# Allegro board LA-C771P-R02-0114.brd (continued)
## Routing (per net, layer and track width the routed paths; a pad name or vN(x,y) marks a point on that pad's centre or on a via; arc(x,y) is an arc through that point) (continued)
DDR_A_D25: length 48
  IN1 w0.127: v3(86.27,43.82) 86.27,42.6 85.79,42.13 85.79,39.88 85.58,39.67 85.11,39.67 84.91,39.87 84.91,42.49 84.43,42.98 84.43,44.87 83.93,45.36 83.93,52.24 85.1,53.41 85.1,55.96 90.15,61.02 90.15,64.42 91.04,65.31 v3(91.04,66.18)
  BOTTOM w0.102: v3(91.04,66.18) 91.72,66.86 92.06,66.86 93.44,68.24 94.73,68.24 96.98,70.49 97.52,70.49 97.66,70.35 97.98,70.35 98.14,70.51 98.45,70.51 UC4.C41 ; JDIMM1.59 84.53,45.64 86.27,43.91 v3(86.27,43.82)
DDR_A_D26: length 47.1
  IN1 w0.127: v3(93.73,65.38) 93.73,64.91 94.87,63.77 94.87,62.18 88.45,55.75 88.45,55.57 88.68,55.34 88.86,55.34 90.36,56.83 90.54,56.83 90.77,56.6 90.77,56.42 88.64,54.29 88.64,51.47 88.51,51.34 88.18,51.34 88.06,51.47 88.06,54.79 87.93,54.92 87.62,54.92 87.47,54.77 87.47,47.05 88.72,45.8 88.72,44.88 v3(88.22,44.38)
  BOTTOM w0.102: v3(88.22,44.38) 87.76,44.38 87.38,44.76 87.38,44.78 87.26,44.91 87.26,45.42 86.93,45.74 JDIMM1.67 ; v3(93.73,65.38) 93.73,65.7 95.95,67.92 95.95,68.1 96.78,68.93 97.34,68.93 97.57,68.7 UC4.A45
DDR_A_D27: length 47.1
  IN1 w0.127: v3(88.6,43.11) 89.3,43.81 89.3,46.27 88.06,47.52 88.06,50.62 88.19,50.75 88.96,50.75 89.22,51.02 89.22,53.98 95.09,59.85 95.09,60.03 94.84,60.28 94.66,60.28 91.64,57.26 91.46,57.26 91.21,57.51 91.21,57.69 95.46,61.93 95.46,64.02 94.34,65.14 v3(94.34,65.38)
  BOTTOM w0.102: UC4.B46 98.24,68.38 97.61,68.38 97.29,68.7 96.87,68.7 96.42,68.25 96.42,68 94.34,65.92 v3(94.34,65.38) ; JDIMM1.69 87.53,45.93 87.81,45.65 87.81,45.14 88.02,44.94 88.45,44.94 88.78,44.61 88.78,43.29 v3(88.6,43.11)
DDR_A_D28: length 48.4
  IN1 w0.127: v3(88.98,64.72) 88.98,61.5 83.93,56.45 83.93,53.89 82.76,52.73 82.76,49.28 81.72,48.24 81.72,45.35 82.11,44.96 82.11,42.74 82.86,41.99 82.86,39.41 83.05,39.21 83.33,39.21 83.52,39.41 83.52,40.97 83.76,41.2 v3(84.18,41.2)
  BOTTOM w0.102: v3(88.98,64.72) 88.98,65.49 89.34,65.84 89.34,66.46 90.86,67.98 92.47,67.98 93.22,68.74 94.54,68.74 96.78,70.98 97.96,70.98 98.15,70.79 98.31,70.79 98.65,71.13 UC4.C40 ; v3(84.18,41.2) 83.63,40.65 JDIMM1.56
DDR_A_D29: length 48.1
  IN1 w0.127: v3(88.4,65.92) 88.4,61.74 84.43,57.78 83.68,57.78 83.34,57.45 83.34,54.14 82.18,52.97 82.18,49.52 81.13,48.48 81.13,45.1 81.53,44.71 81.53,42.5 81.78,42.24 81.78,38.81 82.04,38.55 83.75,38.55 84.23,39.03 v3(84.23,39.91)
  BOTTOM w0.102: v3(88.4,65.92) 88.4,66.31 90.69,68.6 92.78,68.6 93.15,68.97 94.44,68.97 96.67,71.19 98.16,71.19 UC4.B40 ; JDIMM1.58 v3(84.23,39.91)
DDR_A_D30: length 46.5
  IN1 w0.127: v3(87.59,40.03) 87,39.44 87,39.1 87.21,38.88 87.55,38.88 88.34,39.67 88.34,40.54 89.83,42.03 90.01,42.03 90.25,41.79 90.25,41.61 89.53,40.89 89.53,40.71 89.76,40.48 89.94,40.48 90.86,41.4 90.86,45.82 89.81,46.87 89.81,47.83 89.68,47.95 89.09,47.95 88.96,48.08 88.96,48.41 89.09,48.54 89.68,48.54 89.81,48.67 89.81,49.13 89.68,49.26 88.79,49.26 88.64,49.41 88.64,49.68 88.8,49.84 89.68,49.84 89.81,49.97 89.81,53.72 96.04,59.95 96.04,64.92 v3(95.53,65.44)
  BOTTOM w0.102: JDIMM1.68 87.23,39.68 v3(87.59,40.03) ; v3(95.53,65.44) 95.53,66.44 96.58,67.49 98.05,67.49 98.43,67.11 UC4.B48
DDR_A_D31: length 47.1
  IN1 w0.102: 96.04,65.84 96.63,65.26 96.63,64.45
  IN1 w0.127: v3(89.03,40.29) 89.77,39.55 89.77,38.43 89.9,38.3 90.23,38.3 90.36,38.43 90.36,39.41 90.48,39.54 90.81,39.54 90.94,39.41 90.94,38.43 91.07,38.3 91.4,38.3 91.53,38.43 91.53,39.41 92,39.89 92,41.99 91.44,42.55 91.44,46.25 90.39,47.3 90.39,53.17 96.63,59.4 96.63,64.45 ; 96.04,65.84 95.79,66.1 95.18,66.1 94.93,65.84 v3(94.93,65.38)
  BOTTOM w0.102: v3(89.03,40.29) 88.83,40.29 88.17,39.63 87.83,39.29 JDIMM1.70 ; v3(94.93,65.38) 94.99,65.45 94.99,66.19 96.73,67.93 96.73,68.15 96.91,68.33 97.34,68.33 97.5,68.18 97.96,68.18 98.19,67.95 98.19,67.83 UC4.B47
DDR_A_D32: length 47.6
  IN1 w0.102: v3(102.34,62.57) 100.8,62.57 100.35,62.11
  IN1 w0.127: 100.35,62.11 100.08,61.84 99.3,61.84 98.84,61.37 98.84,58.8 92.14,52.1 92.14,50.04 93.08,49.1 93.08,47.36 94.63,45.82 97.82,45.82 98.5,45.14 98.5,43.25 99.07,42.68 101.28,42.68 101.67,42.28 106.58,42.28 107.24,41.63 107.58,41.63 107.86,41.91 107.86,42.54 107.55,42.85 v3(107.55,43.65)
  BOTTOM w0.102: v3(102.34,62.57) 102.57,62.79 102.57,64.11 102.36,64.32 102.36,65.02 UC4.K52 ; JDIMM1.129 107.93,46.01 107.17,45.24 107.17,44.73 107.25,44.66 107.25,44 107.55,43.69 v3(107.55,43.65)
DDR_A_D33: length 48.4
  IN1 w0.127: v3(107.78,44.91) 107.22,44.35 107.22,44.19 106.84,43.81 106.84,43 106.71,42.87 106.38,42.87 105.93,43.33 105.93,44.38 105.7,44.61 105.35,44.61 105.05,44.32 105.05,43.33 104.72,42.99 101.79,42.99 101.52,43.26 100.76,43.26 100.42,43.61 100.42,44.56 98.58,46.4 94.87,46.4 93.95,47.32 93.95,49.83 93.82,49.96 93.06,49.96 92.93,50.08 92.93,50.41 93.06,50.54 93.82,50.54 93.95,50.67 93.95,51 93.82,51.12 93.18,51.12 93.06,51.25 93.06,51.84 93.19,51.98 93.6,51.98 93.73,52.1 93.73,52.86 99.42,58.55 99.42,60.18 101.29,62.04 v3(101.99,62.04)
  BOTTOM w0.102: v3(101.99,62.04) 102.38,62.04 102.77,62.44 102.77,64.23 102.56,64.44 102.56,64.79 102.7,64.93 102.7,65.11 102.48,65.32 102.48,65.6 UC4.K51 ; JDIMM1.131 108.53,45.77 107.78,45.01 v3(107.78,44.91)
DDR_A_D34: length 48.5
  IN1 w0.127: v3(112,45.22) 112,46.8 109.21,49.59 107.65,49.59 107.52,49.46 107.52,49.26 107.4,49.14 107.07,49.14 106.94,49.26 106.94,49.46 106.81,49.59 106.36,49.59 104.54,51.4 104.01,51.4 103.84,51.57 103.84,52.03 104.87,53.06 104.87,53.24 104.64,53.47 104.46,53.47 102.57,51.58 102.39,51.58 102.18,51.79 102.18,52.02 104.05,53.89 104.05,54.15 103.86,54.33 103.67,54.33 100.23,50.9 100.05,50.9 99.82,51.12 99.82,51.32 102.5,54 102.5,54.18 102.27,54.41 102.09,54.41 101.56,53.88 101.38,53.88 101.15,54.11 101.15,54.29 102.06,55.21 103.33,55.21 103.67,55.56 103.67,56.6 v3(103.25,57.02)
  BOTTOM w0.102: v3(112,45.22) 111.92,45.22 111.53,45.6 JDIMM1.141 ; v3(103.25,57.02) 103.25,57.02 103.36,57.12 103.36,58.34 105.38,60.36 105.38,63.44 105.27,63.55 105.27,65.02 UC4.T52
DDR_A_D35: length 49.4
  IN1 w0.127: v3(103.09,56.29) 102.58,56.29 102.14,55.84 101.72,55.84 97.49,51.61 97.49,51.43 97.72,51.2 97.99,51.2 100.41,53.62 100.59,53.62 100.85,53.35 100.85,53.17 98.33,50.65 98.33,50.47 98.81,50 99.14,50 99.45,50.31 101.1,50.31 101.6,50.82 104.3,50.82 106.57,48.54 107.83,48.54 108.29,49 108.97,49 111.41,46.56 111.41,44.43 v3(111.94,43.9)
  BOTTOM w0.102: v3(111.94,43.9) 112.48,44.43 112.48,44.93 112.58,45.04 112.58,45.5 112.13,45.94 JDIMM1.143 ; UC4.T51 105.28,65.44 105.59,65.13 105.59,64.93 105.48,64.81 105.48,64.2 105.94,63.74 105.94,60.13 104.04,58.24 104.04,56.78 103.55,56.29 v3(103.09,56.29)
DDR_A_D36: length 48.5
  IN1 w0.127: v3(108.77,41.56) 108.77,41.09 108.38,40.7 107.34,40.7 106.34,41.7 101.43,41.7 101.04,42.09 98.82,42.09 97.88,43.04 95.3,43.04 93.44,44.9 93.44,46.09 92.5,47.04 92.5,48.86 91.56,49.8 91.56,52.43 v3(98.2,59.07)
  BOTTOM w0.102: v3(108.77,41.56) 108.23,41.02 JDIMM1.130 ; UC4.L51 103.03,65.2 103.03,64.91 103.31,64.63 103.31,62 102.51,61.19 101.12,61.19 101.12,61.19 100.18,60.25 99.51,60.25 98.34,59.07 v3(98.2,59.07)
DDR_A_D37: length 47.5
  IN1 w0.127: v3(108.83,39.91) 108.41,39.49 100.6,39.49 97.64,42.46 94.95,42.46 92.86,44.55 92.86,45.65 91.92,46.59 91.92,48.61 90.98,49.55 90.98,52.93 97.4,59.35 97.4,59.75 97.89,60.24 v3(98.26,60.24)
  BOTTOM w0.102: UC4.L53 103.04,64.45 103.04,62.11 102.34,61.42 100.56,61.42 99.95,60.81 98.83,60.81 v3(98.26,60.24) ; JDIMM1.132 v3(108.83,39.91)
DDR_A_D38: length 48.9
  IN1 w0.127: v3(101.41,57.59) 101,57.59 95.74,52.33 95.74,50.47 98.02,48.19 99.81,48.19 100.17,48.56 101.03,48.56 101.4,48.19 102.6,48.19 104,46.79 108.7,46.79 109.66,45.83 109.66,43.7 109.99,43.37 109.99,42.69 109.42,42.12 109.42,38.12 109.74,37.79 110.91,37.79 111.23,38.11 v3(111.23,39.91)
  BOTTOM w0.102: v3(111.23,39.91) JDIMM1.140 ; v3(101.41,57.59) 101.82,57.59 105.07,60.84 105.07,64.8 105.04,64.83 104.91,64.96 104.87,65 104.87,65.3 UC4.R51
DDR_A_D39: length 48.6
  IN1 w0.127: v3(101.43,58.32) 101.5,58.32 102.1,57.73 102.1,57.46 101.65,57.01 101.24,57.01 96.32,52.09 96.32,50.72 98.26,48.77 99.56,48.77 99.93,49.14 101.28,49.14 101.64,48.77 102.84,48.77 104.24,47.38 108.94,47.38 110.24,46.08 110.24,43.95 110.57,43.62 110.57,42.45 110,41.88 110,38.93 110.13,38.8 110.52,38.8 110.65,38.93 110.65,41.07 110.77,41.2 v3(111.22,41.2)
  BOTTOM w0.102: v3(101.43,58.32) 101.76,58.32 104.8,61.36 104.8,64.32 UC4.R53 ; v3(111.22,41.2) 111.23,41.2 111.83,40.6 JDIMM1.142
DDR_A_D40: length 48.3
  IN1 w0.102: v3(104.8,67.14) 104.16,66.5 104.16,65.65 103.77,65.26 103.77,65.06
  IN1 w0.127: 103.77,65.06 103.77,64.95 103.65,64.83 102.32,64.83 102.17,64.68 102.17,64.19 102.37,63.99 102.87,63.99 103.12,64.24 103.71,64.24 103.84,64.11 103.84,61.48 103.68,61.32 103.05,61.32 102.93,61.19 102.93,60.86 103.05,60.73 103.67,60.73 103.8,60.6 103.8,60.28 103.67,60.15 103.08,60.15 102.95,60.02 102.95,59.69 103.08,59.57 103.59,59.57 103.85,59.3 103.85,58.2 105.42,56.63 105.42,56.45 105.26,56.28 105.26,56.1 105.49,55.87 105.67,55.87 105.84,56.04 106.02,56.04 106.25,55.8 106.25,55.62 105.64,55.01 105.64,54.83 105.87,54.6 106.05,54.6 106.66,55.21 106.84,55.21 107.08,54.98 107.08,54.8 106.49,54.21 106.49,54.03 106.73,53.8 106.91,53.8 107.49,54.38 107.67,54.38 107.9,54.15 107.9,53.97 107.1,53.16 107.1,52.99 107.3,52.79 107.55,52.79 108.32,53.56 108.5,53.56 108.67,53.39 108.67,53.08 108.12,52.53 108.12,52.29 108.31,52.1 108.51,52.1 108.83,52.42 109.01,52.42 109.22,52.21 109.22,51.98 108.43,51.19 108.43,50.96 108.64,50.75 108.82,50.75 109.68,51.61 109.86,51.61 110.09,51.38 110.09,51.2 109.77,50.88 109.77,50.7 110.01,50.47 110.19,50.47 110.43,50.71 110.61,50.71 110.85,50.48 110.85,50.3 110.6,50.05 110.6,49.87 113.52,46.95 113.52,46.44 113.33,46.25 113.33,45.89 113.52,45.7 113.52,45.17 113.33,44.99 v3(113.33,44.57)
  BOTTOM w0.102: JDIMM1.147 v3(113.33,44.57) ; UC4.T47 v3(104.8,67.14)
DDR_A_D41: length 47.3
  IN1 w0.127: v3(113.34,43.29) 112.75,43.88 112.75,46.88 109.45,50.17 106.89,50.17 106.71,50.35 106.71,50.76 107.68,51.73 107.68,51.91 107.45,52.14 107.27,52.14 106.07,50.95 105.82,50.95 105.62,51.15 105.62,51.33 106.68,52.38 106.68,52.56 106.45,52.8 106.27,52.8 105.26,51.79 105.06,51.79 104.84,52.01 104.84,52.19 105.62,52.98 105.62,54.01 104.45,55.18 104.45,56.78 103.27,57.96 103.27,58.21 102.27,59.21 102.27,61.4 103.05,62.18 103.05,63.02 102.77,63.3 100.82,63.3 100.67,63.45 100.67,64.14 102.14,65.61 103.06,65.61 103.28,65.83 103.28,66.8 103.88,67.41 104.31,67.41 v3(104.81,67.91)
  BOTTOM w0.102: JDIMM1.149 113.93,43.88 v3(113.34,43.29) ; UC4.T45 v3(104.81,67.91)
DDR_A_D42: length 47
  IN1 w0.102: 107.17,67.48 107.17,69.37 107.31,69.51 107.31,70.82 v3(106.72,71.41)
  IN1 w0.127: v3(117.25,43.79) 118.02,43.79 118.29,44.07 118.29,45.44 118.86,46.01 119.81,46.01 120.69,46.89 120.69,50.86 120.11,51.44 120.11,51.8 119.71,52.21 119.53,52.21 119.24,51.92 119.06,51.92 118.83,52.15 118.83,52.33 119.06,52.57 119.06,52.86 117.4,54.52 113.45,54.52 107.98,59.98 107.98,63.67 108.14,63.82 108.49,63.82 108.64,63.97 108.64,64.72 108.34,65.01 108.34,66.24 108.21,66.37 107.89,66.37 107.75,66.23 107.75,65.12 107.58,64.95 107.31,64.95 107.17,65.09 107.17,67.48
  BOTTOM w0.102: v3(117.25,43.79) 116.33,44.72 JDIMM1.157 ; UC4.Y40 v3(106.72,71.41)
DDR_A_D43: length 48.1
  IN1 w0.102: v3(106.74,70.78) 106.8,70.78 107.1,70.48 107.1,69.71 106.81,69.42 106.51,69.42 106.2,69.12 106.2,65.87 106.44,65.63 106.44,65.19
  IN1 w0.127: 106.44,65.19 106.44,65.02 106.81,64.65 106.81,64.43 106.44,64.06 106.44,63.84 106.72,63.56 107.18,63.56 107.4,63.34 107.4,59.67 113.13,53.93 116.22,53.93 116.57,53.59 116.75,53.59 117.03,53.88 117.21,53.88 117.45,53.65 117.45,53.47 117.16,53.18 117.16,53 117.39,52.76 117.57,52.76 117.86,53.05 118.04,53.05 118.24,52.85 118.24,51.91 118.94,51.22 118.94,47.41 119.09,47.26 119.4,47.26 119.52,47.39 119.52,50.6 119.65,50.72 119.98,50.72 120.11,50.6 120.11,47.14 119.57,46.59 118.62,46.59 117.71,45.68 117.71,45.18 117.54,45 117.24,45 v3(117.08,45.17)
  BOTTOM w0.102: JDIMM1.159 116.93,45.36 117.08,45.22 v3(117.08,45.17) ; UC4.V41 v3(106.74,70.78)
DDR_A_D44: length 48.3
  IN1 w0.102: v3(104.78,66.51) 104.43,66.16 104.43,62.11 104.44,62.11
  IN1 w0.127: 104.44,62.11 104.44,58.44 111.44,51.44 111.44,49.86 114.1,47.2 114.1,43.12 113.68,42.7 112.12,42.7 111.84,42.42 111.84,37.02 111.72,36.89 109.95,36.89 109.82,36.76 109.82,36.43 109.95,36.3 112.32,36.3 112.71,36.69 112.71,40.65 v3(112.58,40.77)
  BOTTOM w0.102: UC4.T48 v3(104.78,66.51) ; JDIMM1.146 113.03,40.32 v3(112.58,40.77)
DDR_A_D45: length 48.3
  IN1 w0.102: v3(104.82,65.9) 104.82,64.63 105.02,64.42 105.02,62.11
  IN1 w0.127: v3(114,41.28) 114,39.34 114.13,39.21 115.42,39.21 115.56,39.07 115.56,38.75 115.43,38.63 114.13,38.63 114,38.5 114,38.17 114.13,38.04 115.35,38.04 115.48,37.91 115.48,37.58 115.35,37.46 113.6,37.46 113.42,37.64 113.42,41.15 113.11,41.46 112.58,41.46 112.43,41.61 112.43,41.99 112.55,42.12 113.93,42.12 114.69,42.88 114.69,47.44 112.02,50.1 112.02,51.68 105.02,58.68 105.02,62.11
  BOTTOM w0.102: JDIMM1.148 113.63,40.25 113.8,40.42 113.8,40.9 114,41.1 v3(114,41.28) ; UC4.T50 v3(104.82,65.9)
DDR_A_D46: length 48.3
  IN1 w0.102: 109.24,67.48 109.24,68.32 109.03,68.53 108.43,68.53 107.71,69.24 v3(107.71,69.5)
  IN1 w0.127: v3(117.23,41.48) 117.69,41.48 118.16,41.95 118.16,42.21 117.69,42.68 117.69,42.86 117.93,43.09 118.11,43.09 118.58,42.62 118.83,42.62 119.55,43.33 119.55,44.92 121.28,46.65 121.28,51.47 117.64,55.1 113.69,55.1 108.6,60.19 108.6,63.01 109.24,63.64 109.24,65.11 109.36,65.23 110.46,65.23 110.59,65.36 110.59,65.73 110.43,65.89 109.36,65.89 109.24,66.01 109.24,66.34 109.36,66.47 110.14,66.47 110.27,66.6 110.27,66.93 110.14,67.05 109.36,67.05 109.24,67.18 109.24,67.48
  BOTTOM w0.102: UC4.Y42 v3(107.71,69.5) ; v3(117.23,41.48) 116.63,40.88 JDIMM1.158
DDR_A_D47: length 48.1
  IN1 w0.102: 109.62,68.48 109.26,68.84 108.68,68.84 108.17,69.35 108.17,70.45 107.73,70.88 v3(107.73,70.89)
  IN1 w0.127: v3(117.25,39.96) 117.25,38.82 117.38,38.7 117.94,38.7 118.07,38.82 118.07,41.03 120.13,43.09 120.13,44.53 121.86,46.26 121.86,51.71 117.88,55.69 113.93,55.69 109.19,60.43 109.19,62.77 111.47,65.05 111.47,66.63 109.62,68.48
  BOTTOM w0.102: v3(117.25,39.96) 117.25,39.93 117.23,39.91 JDIMM1.160 ; UC4.AB40 v3(107.73,70.89)
DDR_A_D48: length 46.8
  IN2 w0.102: 110.6,63.3 110.25,63.65 109.49,63.65 107.5,65.63 107.5,66.29 107.5,66.35 107.25,66.6 107.25,67.72 v3(106.73,68.25)
  IN2 w0.127: v3(118.78,43.74) 119.12,43.74 119.32,43.94 119.32,45.81 120.96,47.46 120.96,50.47 120.83,50.59 120.5,50.59 120.38,50.47 120.38,47.7 120.24,47.57 119.92,47.57 119.79,47.69 119.79,54.28 117.38,56.69 117.13,56.69 116.97,56.53 116.97,56.28 117.64,55.6 117.64,55.39 117.5,55.24 117.18,55.24 115.73,56.69 114.24,56.69 111.44,59.5 111.44,60.79 110.93,61.29 110.93,62.97 110.6,63.3
  BOTTOM w0.102: JDIMM1.163 118.13,44.39 v3(118.78,43.74) ; UC4.V45 v3(106.73,68.25)
DDR_A_D49: length 48.8
  IN2 w0.102: v3(106.73,67.49) 107.05,67.17 107.05,66.48 107.3,66.23 107.3,65.5 109.48,63.32 109.9,63.32 110.19,63.02
  IN2 w0.127: 110.19,63.02 110.45,62.77 110.45,61.94 110.34,61.84 110.34,61.05 110.85,60.55 110.85,59.26 114.11,56 115.59,56 118.04,53.55 118.04,46.92 118.21,46.75 118.45,46.75 118.62,46.92 118.62,53.8 117.97,54.45 117.97,54.63 118.2,54.87 118.38,54.87 119.21,54.04 119.21,46.53 118.7,46.02 118.29,46.02 118.14,45.87 118.14,45.49 118.36,45.27 v3(118.71,45.27)
  BOTTOM w0.102: v3(118.71,45.27) 118.73,45.29 JDIMM1.165 ; UC4.V47 v3(106.73,67.49)
DDR_A_D50: length 48.8
  IN2 w0.102: 110.71,66.31 110.33,66.31 109.21,67.42 v3(108.75,67.42)
  IN2 w0.127: 110.71,66.31 112.59,66.31 126.56,52.33 126.56,47.38 126.43,47.26 125.3,47.26 125.15,47.11 125.15,46.8 125.28,46.67 126.55,46.67 126.68,46.55 126.68,46.22 126.55,46.09 125.38,46.09 125.2,45.9 125.2,44.14 124.99,43.93 124.75,43.93 124.57,44.11 124.57,45.62 124.42,45.76 124.18,45.76 123.19,44.77 123.19,44.31 123.46,44.04 123.46,43.29 122.73,42.56 122.53,42.56 122.25,42.83 122.25,43.23 v3(122.74,43.72)
  BOTTOM w0.102: UC4.AD48 v3(108.75,67.42) ; JDIMM1.175 121.73,45.14 121.98,44.89 121.98,44.25 122.51,43.72 v3(122.74,43.72)
DDR_A_D51: length 48.4
  IN2 w0.102: v3(108.74,66.69) 109.23,66.2 109.85,66.2 110.4,65.65 111.11,65.65
  IN2 w0.127: 111.11,65.65 112.42,65.65 115.22,62.85 115.22,62.67 114.58,62.03 114.58,61.82 114.78,61.62 115,61.62 115.63,62.25 115.81,62.25 116.05,62.02 116.05,61.84 115.8,61.59 115.8,61.41 116,61.22 116.25,61.22 116.46,61.43 116.64,61.43 116.87,61.19 116.87,61.01 116.68,60.82 116.68,60.62 116.87,60.43 117.12,60.43 117.29,60.6 117.46,60.6 124.62,53.44 124.62,53.25 124.5,53.12 123.72,53.12 123.6,52.99 123.6,52.68 123.74,52.54 124.5,52.54 124.62,52.41 124.62,52.16 124.75,52.03 125.71,52.03 125.84,51.9 125.84,51.57 125.71,51.44 124.75,51.44 124.62,51.32 124.62,50.99 124.75,50.86 125.78,50.86 125.91,50.73 125.91,50.41 125.77,50.28 124.75,50.28 124.62,50.15 124.62,49.82 124.75,49.69 125.77,49.69 125.9,49.56 125.9,49.24 125.77,49.11 124.75,49.11 124.62,48.98 124.62,48.65 124.75,48.52 125.77,48.52 125.9,48.4 125.9,48.07 125.77,47.94 124.71,47.94 124.58,47.81 124.58,47.23 124.45,47.1 124.14,47.1 123.84,47.41 123.65,47.41 123.42,47.18 123.42,47 123.84,46.58 123.84,46.26 123.47,45.88 123.1,45.88 v3(122.43,45.22)
  BOTTOM w0.102: v3(122.43,45.22) 122.43,45.6 122.33,45.7 JDIMM1.177 ; UC4.AD50 v3(108.74,66.69)
DDR_A_D52: length 46.8
  IN2 w0.102: 109.42,62.51 109.42,63.02 107.1,65.34 107.1,66.14 106.67,66.57 v3(106.67,66.67)
  IN2 w0.127: 109.42,62.51 109.42,59.87 113.86,55.42 115.35,55.42 117.46,53.31 117.46,45.35 117.87,44.93 117.87,43.82 117.17,43.12 117.17,42.22 117.85,41.54 117.85,39.15 117.66,38.95 115.5,38.95 115.37,38.83 115.37,38.52 115.52,38.37 118.18,38.37 118.55,38.74 118.55,41.2 118.81,41.46 v3(119.14,41.46)
  BOTTOM w0.102: v3(119.14,41.46) 118.43,40.75 JDIMM1.164 ; UC4.V48 v3(106.67,66.67)
DDR_A_D53: length 48.4
  IN2 w0.102: 108.65,63.42 106.71,65.36 v3(106.71,65.97)
  IN2 w0.127: v3(119.14,39.93) 119.14,38.29 118.64,37.79 118.34,37.79 118.21,37.66 118.21,37.03 118.08,36.91 117.75,36.91 117.63,37.03 117.63,37.66 117.5,37.79 117.17,37.79 117.04,37.66 117.04,37.03 116.91,36.91 116.58,36.91 116.46,37.03 116.46,37.66 116.33,37.79 116,37.79 115.87,37.66 115.87,37.03 115.75,36.91 115.42,36.91 115.29,37.03 115.29,37.66 114.78,38.16 114.78,39.16 115.16,39.54 116.36,39.54 116.62,39.8 116.62,40.82 115.12,42.33 115.12,44.76 116.87,46.51 116.87,53.07 115.1,54.84 113.62,54.84 108.83,59.63 108.83,63.24 108.65,63.42
  BOTTOM w0.102: JDIMM1.166 119.03,39.83 v3(119.14,39.93) ; UC4.V50 v3(106.71,65.97)
DDR_A_D54: length 48.5
  IN2 w0.102: 111.33,66.91 110.47,66.91 108.67,68.71 v3(107.69,68.71)
  IN2 w0.127: v3(121.58,39.93) 121.58,38.15 121.72,38.01 122.08,38.01 122.21,38.14 122.21,41.22 123.61,42.61 124.5,42.61 125.49,43.61 126.1,43.61 126.78,44.29 126.78,45.24 127.54,45.99 127.54,52.18 112.81,66.91 111.33,66.91
  BOTTOM w0.102: v3(121.58,39.93) 121.43,39.79 JDIMM1.174 ; UC4.AB44 v3(107.69,68.71)
DDR_A_D55: length 48.7
  IN2 w0.102: v3(106.75,68.91) 107.32,68.91 107.5,69.09 107.86,69.09 108,68.95 108.93,68.95 110.25,67.63 111.29,67.63
  IN2 w0.127: 111.29,67.63 112.92,67.63 128.3,52.24 128.3,44.77 126.55,43.02 125.74,43.02 125.36,42.65 125.36,41.1 125.23,40.97 124.85,40.97 124.73,41.1 124.73,41.8 124.5,42.03 123.91,42.03 v3(122.8,40.92)
  BOTTOM w0.102: JDIMM1.176 122.03,39.6 122.18,39.75 122.18,40.3 v3(122.8,40.92) ; UC4.Y45 v3(106.75,68.91)
DDR_A_D56: length 49.1
  IN1 w0.127: v3(124.11,43.57) 122.7,42.15 122.28,42.15 121.99,42.45 121.99,45.57 122.45,46.02 122.45,50.55 122.57,50.68 122.88,50.68 123.03,50.53 123.03,46.34 123.16,46.22 123.49,46.22 123.61,46.34 123.61,50.79 118.12,56.28 114.25,56.28 v3(110.34,60.18)
  BOTTOM w0.102: UC4.V52 106.17,64.94 106.17,63.26 109.38,60.05 110.22,60.05 v3(110.34,60.18) ; JDIMM1.181 123.53,44.15 v3(124.11,43.57)
DDR_A_D57: length 48.6
  IN1 w0.127: v3(124.13,44.98) 123.35,44.2 123.06,44.2 122.92,44.34 122.92,45.39 123.17,45.63 123.73,45.63 124.2,46.1 124.2,52.68 120.19,56.68 120.01,56.68 119.8,56.47 119.8,56.25 123.6,52.45 123.6,52.27 123.37,52.04 123.18,52.04 118.26,56.96 114.44,56.96 110.61,60.79 110.12,60.79 v3(109.89,60.56)
  BOTTOM w0.102: v3(109.89,60.56) 109.78,60.56 108.83,61.51 108.45,61.51 106.45,63.51 106.45,64.8 106.58,64.92 106.58,65.22 UC4.W51 ; JDIMM1.183 v3(124.13,44.98)
DDR_A_D58: length 49.8
  IN1 w0.102: v3(113.54,62.73) 114.06,62.73 115.18,61.62 115.18,61.31 115.38,61.1
  IN1 w0.127: v3(128.12,42.63) 128.12,42.86 127.67,43.32 127.67,43.44 128.12,43.9 128.12,55.42 127.44,56.1 127.44,56.35 127.62,56.53 128.58,56.53 128.7,56.4 128.7,54.71 128.83,54.59 129.16,54.59 129.29,54.71 129.29,56.71 125.61,60.39 124.45,60.39 124.09,60.03 123.54,60.03 122.51,61.05 115.43,61.05 115.38,61.1
  BOTTOM w0.102: JDIMM1.191 126.53,44.22 v3(128.12,42.63) ; v3(113.54,62.73) 112.39,62.73 111.96,63.17 109.37,63.17 108.68,63.86 108.68,64.63 UC4.AC53
DDR_A_D59: length 50.1
  IN1 w0.102: 115.92,61.64 115.64,61.64 114.1,63.18 v3(113.05,63.18)
  IN1 w0.127: v3(128.7,43.85) 128.7,53.85 128.86,54 129.16,54 129.29,53.88 129.29,50.66 129.42,50.53 129.75,50.53 129.87,50.66 129.87,56.95 125.85,60.98 123.41,60.98 122.75,61.64 115.92,61.64
  BOTTOM w0.102: v3(113.05,63.18) 112.48,63.18 112.23,63.43 109.51,63.43 109,63.95 109,64.76 108.68,65.09 UC4.AC51 ; v3(128.7,43.85) 128.12,43.85 127.13,44.84 JDIMM1.193
DDR_A_D60: length 49.3
  IN1 w0.127: v3(124.22,41.46) 123.42,40.66 123.42,39.06 123.14,38.79 122.54,38.79 122.41,38.92 122.41,39.29 122.29,39.42 121.96,39.42 121.83,39.29 121.83,38.89 121.7,38.77 121.29,38.77 121.16,38.89 121.16,40.87 121.76,41.47 123.06,41.47 124.78,43.19 124.78,52.92 120.16,57.54 114.68,57.54 110.44,61.78 v3(109.81,61.78)
  BOTTOM w0.102: JDIMM1.180 123.23,40.47 v3(124.22,41.46) ; v3(109.81,61.78) 108.55,61.78 106.74,63.59 106.74,64.63 UC4.W53
DDR_A_D61: length 49.8
  IN1 w0.127: v3(111.6,61.45) 114.45,58.6 119.93,58.6 125.37,53.16 125.37,42.95 124.97,42.56 124.97,39.48 125.13,39.32 128.25,39.32 128.4,39.17 128.4,38.87 128.27,38.74 124.38,38.74 124.22,38.9 v3(124.22,40.04)
  BOTTOM w0.102: JDIMM1.182 123.83,39.65 v3(124.22,40.04) ; v3(111.6,61.45) 111.52,61.52 110.95,61.52 110.29,62.18 108.43,62.18 107.02,63.6 107.02,64.8 106.9,64.92 106.9,65.12 107.04,65.27 107.04,65.54 UC4.Y51
DDR_A_D62: length 48.6
  IN1 w0.102: 115.3,63.12 114.76,63.67 v3(112.57,63.67)
  IN1 w0.127: v3(127.54,41.33) 127.69,41.18 127.98,41.18 128.38,41.58 128.38,41.91 128.63,42.17 128.97,42.17 129.29,42.49 129.29,47.65 129.42,47.78 129.74,47.78 130.04,47.48 130.29,47.48 130.46,47.65 130.46,49.1 130.2,49.36 129.46,49.36 129.29,49.52 129.29,49.75 129.46,49.92 130.2,49.92 130.46,50.17 130.46,57.2 125.43,62.22 116.2,62.22 115.3,63.12
  BOTTOM w0.102: v3(127.54,41.33) 126.83,40.63 JDIMM1.192 ; UC4.AD52 109.3,64.89 109.3,64.03 109.64,63.69 112.55,63.69 v3(112.57,63.67)
DDR_A_D63: length 49.8
  IN1 w0.102: v3(113.02,64.15) 113.18,63.99 115.3,63.99 115.72,63.57
  IN1 w0.127: 115.72,63.57 116.49,62.81 125.67,62.81 131.04,57.44 131.04,45.92 130.87,45.75 130.63,45.75 130.46,45.92 130.46,46.7 130.29,46.87 130.04,46.87 129.87,46.7 129.87,42.25 129.66,42.03 129.66,41.85 130.04,41.46 130.04,41.22 129.87,41.05 129.63,41.05 129.24,41.44 129.06,41.44 v3(127.56,39.93)
  BOTTOM w0.102: UC4.AD51 109.29,65.62 109.29,65.32 109.57,65.04 109.69,65.04 110.06,64.67 110.06,64.65 110.61,64.1 112.42,64.1 112.47,64.15 v3(113.02,64.15) ; v3(127.56,39.93) 127.43,39.81 JDIMM1.194
DDR_A_DM0: length 73
  IN1 w0.102: 99.9,72.16 100.08,72.16 v3(100.53,72.6)
  IN1 w0.127: v3(70.01,45.39) 70.01,45.88 69.63,46.26 69.63,47.96 69.25,48.35 69.25,58.51 69.42,58.68 69.66,58.68 69.83,58.51 69.83,51.25 70,51.08 70.24,51.08 70.41,51.25 70.41,65.37 79.14,74.1 91.55,74.1 93.22,72.43 96.25,72.43 96.52,72.16 99.9,72.16
  BOTTOM w0.102: UC4.G36 v3(100.53,72.6) ; JDIMM1.11 70.13,45.52 v3(70.01,45.39)
DDR_A_DM1: length 56.9
  IN1 w0.127: v3(91.5,69.43) 91.5,70 90.35,71.15 87.68,71.15 84.53,68 80.68,68 78.24,65.56 78.24,62.73 76.87,61.36 76.87,50.09 75.67,48.89 75.67,42.9 75.88,42.69 75.88,38.55 75.69,38.36 75.41,38.36 75.24,38.53 75.24,39.88 v3(75.36,40)
  BOTTOM w0.102: v3(75.36,40) 75.23,39.87 JDIMM1.28 ; UC4.B36 98.22,73.07 95.82,73.07 93.46,70.71 92.67,70.71 91.5,69.54 v3(91.5,69.43)
DDR_A_DM2: length 71.9
  IN2 w0.102: v3(99.9,71.63) 100.28,72.02 100.69,72.02 100.93,71.77 100.93,71.46 100.52,71.04 98.91,71.04 98.5,71.45 98.5,71.84 97.69,72.65 95.15,72.65
  IN2 w0.127: 95.15,72.65 78.95,72.65 72.57,66.27 72.57,61.11 72.7,60.99 73.51,60.99 73.68,60.82 73.68,60.57 73.51,60.4 72.7,60.4 72.57,60.28 72.57,59.95 72.7,59.82 74.16,59.82 74.33,59.65 74.33,59.41 74.16,59.24 72.7,59.24 72.57,59.11 72.57,58.78 72.7,58.65 74.64,58.65 74.81,58.48 74.81,50.83 80.3,45.34 80.3,43.06 80.65,42.71 80.65,41.76 80.17,41.28 80.17,40.5 v3(80.63,40.03)
  BOTTOM w0.102: UC4.F38 v3(99.9,71.63) ; JDIMM1.46 v3(80.63,40.03)
DDR_A_DM3: length 46.8
  IN1 w0.127: v3(91.95,66.26) 91.66,65.98 91.66,65.11 90.73,64.18 90.73,63.87 90.86,63.74 91.47,63.74 91.6,63.61 91.6,63.28 91.47,63.16 90.86,63.16 90.73,63.03 90.73,62.7 90.86,62.57 91.47,62.57 91.6,62.44 91.6,62.11 91.47,61.99 90.86,61.99 90.73,61.86 90.73,60.77 85.68,55.72 85.68,50.28 85.56,50.16 85.25,50.16 85.1,50.31 85.1,52.07 84.97,52.2 84.71,52.2 84.51,52 84.51,45.6 85.01,45.11 85.01,43.22 85.19,43.04 85.43,43.04 85.6,43.21 85.6,44.83 85.93,45.16 v3(86.32,45.16)
  BOTTOM w0.102: v3(86.32,45.16) 85.73,45.75 JDIMM1.63 ; UC4.B42 98.14,70.08 97.64,70.08 97.44,70.28 97.05,70.28 94.76,67.99 93.49,67.99 91.95,66.45 v3(91.95,66.26)
DDR_A_DM4: length 48.1
  IN1 w0.127: v3(101.4,59.03) 101.62,59.03 102.69,57.97 102.69,57.22 101.89,56.42 101.48,56.42 96.91,51.85 96.91,50.96 98.5,49.36 99.32,49.36 99.69,49.73 101.34,49.73 101.85,50.24 102.97,50.24 103.17,50.03 103.17,49.27 103.3,49.15 103.63,49.15 103.76,49.27 103.76,50.04 103.88,50.16 104.13,50.16 105.31,48.99 105.31,48.81 104.89,48.39 104.89,48.21 105.12,47.98 105.3,47.98 105.72,48.39 105.9,48.39 106.33,47.96 109.18,47.96 110.83,46.32 110.83,44.19 111.57,43.44 111.57,43.03 111.21,42.67 v3(111.21,42.47)
  BOTTOM w0.102: v3(111.21,42.47) 110.03,41.3 JDIMM1.136 ; v3(101.4,59.03) 101.68,59.03 104.5,61.85 104.5,64.79 104.64,64.93 104.64,65.11 104.31,65.44 UC4.P51
DDR_A_DM5: length 48.3
  IN1 w0.102: 106.81,62.11 106.81,62.62 105.85,63.59 105.85,69.52 106.34,70.01 v3(106.72,70.01)
  IN1 w0.127: v3(116.49,43.46) 116.49,43.88 116.68,44.08 116.68,44.7 116.49,44.9 116.49,45.73 116.65,45.89 117.05,45.89 117.22,46.06 117.22,46.24 116.49,46.96 116.49,47.24 116.64,47.39 116.89,47.39 117.65,46.63 117.83,46.63 118.24,47.04 118.24,49.51 117.83,49.92 117.83,50.1 118.36,50.63 118.36,50.9 118.19,51.07 117.97,51.07 117.42,50.51 117.24,50.51 117,50.75 117,50.93 117.61,51.54 117.61,51.72 117.38,51.95 117.2,51.95 116.54,51.29 116.36,51.29 116.12,51.52 116.12,51.7 116.79,52.36 116.79,52.54 116.55,52.78 116.37,52.78 115.76,52.17 115.59,52.17 115.35,52.4 115.35,52.58 115.69,52.92 115.69,53.11 115.46,53.34 115.28,53.34 114.94,52.99 114.76,52.99 114.4,53.35 112.89,53.35 106.81,59.43 106.81,62.11
  BOTTOM w0.102: UC4.V42 v3(106.72,70.01) ; JDIMM1.153 115.13,44.32 115.98,43.46 v3(116.49,43.46)
DDR_A_DM6: length 49
  IN2 w0.102: v3(107.71,66.72) 107.71,65.79 108.44,65.07 109.65,65.07 112.02,62.69 112.02,61.73
  IN2 w0.127: 112.02,61.73 112.02,59.74 114.49,57.27 117.62,57.27 120.38,54.52 120.38,51.37 120.5,51.25 120.83,51.25 120.96,51.37 120.96,53.1 121.09,53.23 121.42,53.23 121.55,53.1 121.55,47.22 119.9,45.57 119.9,43.15 119.77,43.02 118.28,43.02 118.11,42.85 118.11,42.61 118.28,42.44 119.68,42.44 119.91,42.21 119.91,40.39 120.16,40.14 120.52,40.14 120.77,40.39 120.77,41.19 v3(120.5,41.46)
  BOTTOM w0.102: v3(120.5,41.46) 120.85,41.11 120.85,40.47 120.38,40 120.38,39.8 120.23,39.66 JDIMM1.170 ; UC4.Y50 v3(107.71,66.72)
DDR_A_DM7: length 48.3
  IN1 w0.127: v3(125.97,44.29) 126.23,44.56 126.23,54.78 122.44,58.57 122.26,58.57 122.04,58.34 122.04,58.14 125.58,54.6 125.58,54.36 125.38,54.16 125.2,54.16 120.17,59.18 114.7,59.18 111.83,62.06 v3(111.36,62.06)
  BOTTOM w0.102: JDIMM1.187 125.33,44.93 v3(125.97,44.29) ; v3(111.36,62.06) 111.03,62.39 108.52,62.39 107.22,63.68 107.22,65.02 UC4.Y52
DDR_A_DQS0: length 72.6
  IN1 w0.102: v3(101.93,72.6) 102.13,72.79 102.13,72.96 101.76,73.32 98.38,73.32 97.71,73.99 96.06,73.99 96.04,73.98
  IN1 w0.127: 96.04,73.98 93.57,73.98 92.07,75.48 78.58,75.48 69.07,65.97 69.07,62.46 67.9,61.3 67.9,47.79 68.28,47.41 68.28,45.62 68.47,45.43 68.47,41.88 68.03,41.44 68.03,39.95 68.24,39.74 68.56,39.74 68.8,39.97 68.8,40.74 69.16,41.1 69.7,41.1 70.02,40.78 70.02,40.33 70.16,40.19 70.33,40.19 v3(70.44,40.3)
  BOTTOM w0.102: JDIMM1.12 70.43,39.34 70.05,39.72 70.05,40.28 70.16,40.39 70.35,40.39 v3(70.44,40.3) ; UC4.J38 v3(101.93,72.6)
DDR_A_DQS1: length 56.5
  IN1 w0.127: v3(90.73,69.38) 90.51,69.6 90.51,69.9 90.02,70.39 87.99,70.39 85.03,67.43 85.03,63.14 83.04,61.14 80.2,61.14 79.8,60.75 79.8,58.95 79.48,58.63 79.09,58.63 78.89,58.83 78.89,60.9 78.56,61.23 78.02,61.23 77.63,60.84 77.63,49.74 76.43,48.54 76.43,46.13 77,45.56 77,44.51 76.87,44.38 76.58,44.38 v3(76.44,44.53)
  BOTTOM w0.102: UC4.C35 98.42,73.72 98.12,73.72 97.95,73.89 95.95,73.89 93.35,71.28 91.7,71.28 90.56,70.14 90.56,69.55 v3(90.73,69.38) ; JDIMM1.29 75.53,45.6 75.34,45.41 75.34,44.51 75.59,44.26 76.17,44.26 v3(76.44,44.53)
DDR_A_DQS2: length 72.8
  IN2 w0.102: v3(99.24,70.64) 99.02,70.64 98.29,71.37 98.29,71.65 97.66,72.28 96.16,72.28 95.46,71.58 95.19,71.58 95.18,71.6 95.15,71.6
  IN2 w0.127: 95.15,71.6 87.36,71.6 87.03,71.27 87.03,70.68 86.83,70.49 83.21,70.49 83.08,70.61 83.08,71.12 82.8,71.4 82.07,71.4 81.78,71.12 81.78,70.61 81.66,70.49 81.15,70.49 81.02,70.61 81.02,70.94 80.59,71.37 80.13,71.37 79.25,70.49 78.36,70.49 75.57,67.7 75.57,66.8 75.11,66.34 74.08,66.34 73.75,66.02 73.75,65.55 74.08,65.23 75.44,65.23 75.57,65.1 75.57,64.77 75.44,64.64 73.8,64.64 73.51,64.36 73.51,63.81 73.8,63.52 75.44,63.52 75.57,63.4 75.57,63.07 75.44,62.94 73.8,62.94 73.51,62.66 73.51,62.11 73.8,61.82 75.44,61.82 75.57,61.7 75.57,61.36 75.44,61.24 75,61.24 74.67,60.91 74.67,60.45 75,60.12 75.44,60.12 75.57,59.99 75.57,51.52 81.29,45.8 81.29,45.14 81.7,44.74 81.7,43.86 81.57,43.73 81.23,43.73 81.11,43.86 v3(81.11,44.1)
  BOTTOM w0.102: UC4.D40 99.7,70.94 99.7,70.88 99.45,70.64 v3(99.24,70.64) ; v3(81.11,44.1) 81.16,44.05 81.16,43.8 81.1,43.74 81.01,43.74 80.79,43.74 80.55,43.98 80.55,45.57 80.64,45.66 80.84,45.66 80.93,45.75 JDIMM1.47
DDR_A_DQS3: length 47.1
  IN1 w0.127: v3(94.67,67.19) 94.42,66.93 94.42,66.45 94.11,66.15 93.29,66.15 92.69,65.55 92.69,63.89 92.86,63.72 93.83,63.72 94.11,63.43 94.11,62.7 93.83,62.42 92.85,62.42 92.69,62.26 92.69,61.22 86.71,55.24 86.71,49.41 86.4,49.1 85.67,49.1 85.54,48.98 85.54,48.47 85.67,48.34 86.43,48.34 86.71,48.06 86.71,47.33 86.43,47.05 85.69,47.05 85.54,46.9 85.54,46.41 85.67,46.28 87.16,46.28 87.46,45.98 87.46,42.97 88.34,42.08 88.34,41.61 88.06,41.33 86.92,41.33 86.59,40.99 v3(86.59,40.83)
  BOTTOM w0.102: v3(86.59,40.83) 86.59,41.08 86.47,41.2 86.1,41.2 85.85,40.94 85.85,40.32 85.65,40.12 85.65,39.95 85.75,39.85 85.93,39.85 86.03,39.75 JDIMM1.64 ; UC4.B44 98.18,69.15 96.65,69.15 95.01,67.51 94.71,67.51 94.59,67.38 94.59,67.27 v3(94.67,67.19)
DDR_A_DQS4: length 48.2
  IN1 w0.127: v3(101.41,60.21) 101.29,60.33 101.03,60.33 100.56,59.86 100.56,58.23 94.98,52.65 94.98,50.07 95.46,49.58 95.46,47.81 95.84,47.43 100.32,47.43 100.61,47.15 100.61,45.83 100.81,45.62 101.16,45.62 101.37,45.83 101.37,47.15 101.65,47.43 102.28,47.43 103.01,46.7 103.01,46.18 103.16,46.03 108.12,46.03 108.9,45.25 108.9,43.24 109.07,43.06 v3(109.19,43.06)
  BOTTOM w0.102: v3(109.19,43.06) 108.94,43.06 108.83,43.17 108.83,43.5 109.09,43.75 110.27,43.75 110.52,44.01 110.52,44.79 110.27,45.04 110.08,45.04 109.95,45.17 109.95,45.53 110.05,45.63 110.25,45.63 110.33,45.71 JDIMM1.137 ; UC4.N53 103.73,64.55 103.73,64.29 104.17,63.85 104.17,62.05 102.48,60.37 101.57,60.37 v3(101.41,60.21)
DDR_A_DQS5: length 47.4
  IN1 w0.102: 106.05,62.11 106.05,62.13 106.04,62.15 106.04,62.55 105.56,63.02 105.56,68.86 105.17,69.26 104.96,69.26 v3(104.75,69.47)
  IN1 w0.127: v3(115.7,40.54) 115.54,40.71 115.54,41.07 115.1,41.51 115.1,41.84 115.73,42.47 115.73,47.85 113.05,50.53 113.05,50.83 113.29,51.06 113.59,51.06 116.5,48.16 117,48.16 117.31,48.47 117.31,49.18 113.91,52.59 112.58,52.59 106.05,59.11 106.05,62.11
  BOTTOM w0.102: UC4.T42 v3(104.75,69.47) ; v3(115.7,40.54) 115.56,40.4 115.56,39.81 115.43,39.68 JDIMM1.154
DDR_A_DQS6: length 48.2
  IN2 w0.102: v3(107.68,68.1) 107.68,67.82 107.78,67.72 108.11,67.72 108.33,67.5 108.33,65.9 108.63,65.6 109.88,65.6 110.53,64.95 110.71,64.95 113.05,62.61 113.05,62.02 113.06,62.01 113.06,61.98
  IN2 w0.127: v3(121.49,43.31) 121.49,43.08 121.39,42.98 121.11,42.98 120.93,43.17 120.93,45.14 122.58,46.79 122.58,47.97 122.71,48.11 123.35,48.11 123.75,48.51 123.75,49.12 123.46,49.4 122.71,49.4 122.58,49.53 122.58,50.04 122.71,50.16 123.46,50.16 123.74,50.45 123.74,51.5 123.36,51.88 122.7,51.88 122.58,52.01 122.58,54.08 118.25,58.4 117.73,58.4 117.6,58.53 117.6,58.74 117.32,59.03 116.59,59.03 116.31,58.74 116.31,58.46 116.16,58.31 115.25,58.31 115.06,58.5 115.06,58.94 115.91,59.78 115.91,60.23 115.43,60.71 115,60.71 114.23,59.94 113.72,59.94 113.06,60.59 113.06,61.98
  BOTTOM w0.102: JDIMM1.171 120.53,45.73 120.4,45.6 120.4,43.24 120.61,43.03 121.22,43.03 v3(121.49,43.31) ; UC4.Y47 v3(107.68,68.1)
DDR_A_DQS7: length 49.2
  IN1 w0.127: v3(125.91,41.08) 126.23,41.41 126.52,41.41 127.08,41.97 127.08,42.82 126.65,43.26 126.65,43.5 127.26,44.12 127.26,55.2 126.3,56.17 126.3,56.29 127.26,57.26 127.26,57.66 126.77,58.15 126.32,58.15 125.41,57.24 125.23,57.24 124.87,57.6 124.87,57.78 125.81,58.72 125.81,59.12 125.29,59.63 124.89,59.63 123.95,58.69 123.77,58.69 122.17,60.29 115.06,60.29 114.59,60.76 114.59,61.4 v3(113.99,62)
  BOTTOM w0.102: v3(125.91,41.08) 125.91,41.31 125.76,41.46 125.6,41.46 125.43,41.29 125.43,39.63 125.63,39.43 JDIMM1.188 ; v3(113.99,62) 113.86,61.87 112.44,61.87 111.46,62.84 109.13,62.84 108.32,63.66 108.32,64.89 UC4.AB52
DDR_A_DQS#0: length 72.4
  IN1 w0.102: 96.04,74.24 96.06,74.24 96.07,74.23 97.81,74.23 98.48,73.56 101.86,73.56 102.37,73.06 102.37,72.76 v3(102.53,72.59)
  IN1 w0.127: v3(69.58,40.3) 69.75,40.48 69.75,40.67 69.59,40.84 69.27,40.84 69.07,40.63 69.07,39.86 68.67,39.47 68.13,39.47 67.76,39.84 67.76,41.55 68.21,41.99 68.21,45.32 68.01,45.51 68.01,47.3 67.63,47.68 67.63,61.41 68.8,62.57 68.8,66.08 78.47,75.75 92.18,75.75 93.68,74.24 96.04,74.24
  BOTTOM w0.102: UC4.K38 v3(102.53,72.59) ; JDIMM1.10 69.83,40.04 v3(69.58,40.3)
DDR_A_DQS#1: length 56.5
  IN1 w0.127: v3(76.44,43.76) 76.44,44.03 76.52,44.11 76.98,44.11 77.27,44.4 77.27,45.67 76.7,46.24 76.7,48.43 77.9,49.63 77.9,60.73 78.13,60.97 78.45,60.97 78.62,60.79 78.62,58.72 78.98,58.36 79.59,58.36 80.07,58.84 80.07,60.64 80.31,60.88 83.15,60.88 85.3,63.03 85.3,67.32 88.1,70.12 89.91,70.12 90.24,69.79 90.24,69.58 v3(90.08,69.42)
  BOTTOM w0.102: UC4.B34 98.17,74.1 95.86,74.1 93.26,71.5 91.61,71.5 90.34,70.23 90.34,69.68 v3(90.08,69.42) ; JDIMM1.27 74.93,45.6 75.12,45.41 75.12,44.42 75.5,44.04 76.16,44.04 v3(76.44,43.76)
DDR_A_DQS#2: length 72.9
  IN2 w0.102: 95.15,71.33 95.17,71.33 95.18,71.34 95.56,71.34 96.26,72.04 97.56,72.04 98.05,71.55 98.05,71.27 99.06,70.25 99.34,70.25 v3(99.92,70.57)
  IN2 w0.127: 95.15,71.33 87.47,71.33 87.29,71.16 87.29,70.57 86.94,70.22 83.1,70.22 82.81,70.5 82.81,71.01 82.69,71.14 82.18,71.14 82.05,71.01 82.05,70.5 81.77,70.22 81.04,70.22 80.75,70.5 80.75,70.83 80.48,71.1 80.24,71.1 79.36,70.22 78.47,70.22 75.84,67.59 75.84,66.69 75.22,66.08 74.19,66.08 74.02,65.91 74.02,65.66 74.19,65.49 75.55,65.49 75.84,65.21 75.84,64.66 75.55,64.37 73.91,64.37 73.78,64.25 73.78,63.92 73.91,63.79 75.55,63.79 75.84,63.51 75.84,62.96 75.55,62.67 73.91,62.67 73.78,62.55 73.78,62.22 73.91,62.09 75.55,62.09 75.84,61.81 75.84,61.25 75.55,60.97 75.11,60.97 74.94,60.8 74.94,60.56 75.11,60.39 75.55,60.39 75.84,60.1 75.84,51.63 81.56,45.91 81.56,45.25 81.96,44.85 81.96,43.75 81.68,43.46 81.24,43.46 v3(81.11,43.33)
  BOTTOM w0.102: JDIMM1.45 80.33,44.06 80.33,43.89 80.7,43.52 80.92,43.52 v3(81.11,43.33) ; UC4.F40 v3(99.92,70.57)
DDR_A_DQS#3: length 47.1
  IN1 w0.127: v3(94.06,67.21) 94.15,67.12 94.15,66.56 94,66.41 93.18,66.41 92.42,65.66 92.42,63.77 92.75,63.45 93.72,63.45 93.85,63.32 93.85,62.81 93.72,62.69 92.74,62.69 92.42,62.37 92.42,61.33 86.44,55.35 86.44,49.52 86.29,49.37 85.56,49.37 85.27,49.09 85.27,48.36 85.56,48.08 86.32,48.08 86.44,47.95 86.44,47.44 86.32,47.31 85.57,47.31 85.27,47.01 85.27,46.3 85.56,46.02 87.04,46.02 87.19,45.87 87.19,42.86 88.07,41.97 88.07,41.72 87.95,41.6 v3(86.59,41.6)
  BOTTOM w0.102: v3(94.06,67.21) 94.11,67.21 94.62,67.72 94.92,67.72 96.56,69.36 97.98,69.36 98.29,69.68 UC4.C43 ; v3(86.59,41.6) 86.4,41.41 86.02,41.41 85.64,41.03 85.64,40.41 85.43,40.21 JDIMM1.62
DDR_A_DQS#4: length 48.2
  IN1 w0.127: v3(108.42,43.06) 108.63,43.27 108.63,45.14 108.01,45.76 103.05,45.76 102.74,46.07 102.74,46.59 102.17,47.16 101.76,47.16 101.63,47.03 101.63,45.72 101.27,45.36 100.7,45.36 100.34,45.72 100.34,47.03 100.21,47.16 95.73,47.16 95.19,47.7 95.19,49.47 94.71,49.96 94.71,52.76 100.29,58.34 100.29,59.97 100.92,60.6 101.19,60.6 v3(101.41,60.81)
  BOTTOM w0.102: JDIMM1.135 109.73,45.09 109.99,44.82 110.18,44.82 110.31,44.7 110.31,44.1 110.18,43.97 109,43.97 108.62,43.59 108.62,43.26 v3(108.42,43.06) ; v3(101.41,60.81) 101.41,60.83 101.58,60.66 102.47,60.66 103.95,62.14 103.95,63.76 103.51,64.2 103.51,64.84 UC4.M52
DDR_A_DQS#5: length 47.5
  IN1 w0.102: v3(104.84,68.68) 104.84,68.94 104.92,69.02 105.07,69.02 105.32,68.76 105.32,62.92 105.8,62.45 105.8,62.15 105.78,62.13 105.78,62.11
  IN1 w0.127: 105.78,62.11 105.78,59 112.46,52.32 113.79,52.32 117.04,49.07 117.04,48.58 116.89,48.42 116.61,48.42 113.7,51.33 113.18,51.33 112.79,50.94 112.79,50.42 115.46,47.74 115.46,42.58 114.83,41.95 114.83,41.4 115.27,40.96 115.27,40.76 v3(115.02,40.51)
  BOTTOM w0.102: v3(115.02,40.51) 115.15,40.51 115.34,40.32 115.34,39.9 114.83,39.38 JDIMM1.152 ; UC4.T44 v3(104.84,68.68)
DDR_A_DQS#6: length 48.2
  IN2 w0.102: v3(107.64,67.32) 107.79,67.48 108.01,67.48 108.09,67.4 108.09,65.8 108.53,65.36 109.78,65.36 110.36,64.78 110.43,64.71 110.61,64.71 112.81,62.51 112.81,62.02 112.79,62.01 112.79,61.98
  IN2 w0.127: 112.79,61.98 112.79,60.48 113.61,59.67 114.34,59.67 115.11,60.44 115.32,60.44 115.64,60.12 115.64,59.89 114.8,59.05 114.8,58.39 115.14,58.04 116.27,58.04 116.57,58.35 116.57,58.63 116.7,58.76 117.21,58.76 117.33,58.63 117.33,58.42 117.62,58.14 118.14,58.14 122.31,53.97 122.31,51.9 122.59,51.61 123.25,51.61 123.47,51.39 123.47,50.56 123.34,50.43 122.6,50.43 122.32,50.15 122.32,49.42 122.6,49.14 123.35,49.14 123.48,49.01 123.48,48.62 123.24,48.37 122.6,48.37 122.31,48.08 122.31,46.9 120.66,45.25 120.66,43.06 121,42.72 121.32,42.72 v3(121.49,42.54)
  BOTTOM w0.102: UC4.Y48 v3(107.64,67.32) ; v3(121.49,42.54) 121.22,42.82 120.52,42.82 120.19,43.15 120.19,45.53 119.93,45.79 JDIMM1.169
DDR_A_DQS#7: length 49.3
  IN1 w0.127: v3(113.89,61.31) 114.02,61.45 114.16,61.45 114.32,61.29 114.32,60.65 114.94,60.03 122.06,60.03 123.66,58.43 124.06,58.43 125,59.37 125.18,59.37 125.54,59 125.54,58.83 124.6,57.89 124.6,57.49 125.12,56.97 125.52,56.97 126.43,57.88 126.66,57.88 127,57.55 127,57.37 126.03,56.4 126.03,56.06 127,55.09 127,44.23 126.38,43.61 126.38,43.14 126.82,42.71 126.82,42.08 126.41,41.67 126.07,41.67 v3(125.91,41.84)
  BOTTOM w0.102: JDIMM1.186 125.03,39.49 125.22,39.67 125.22,41.38 125.51,41.67 125.74,41.67 v3(125.91,41.84) ; v3(113.89,61.31) 113.89,61.56 113.8,61.65 112.35,61.65 111.37,62.63 109.04,62.63 108.1,63.57 108.1,64.53 107.83,65.07 107.71,65.19 UC4.AA51
DDR_A_MA0: length 44.8
  IN2 w0.102: 96.44,61.47 97.39,62.43 98.29,62.43 99.48,63.62 99.48,63.81 99.62,63.95 99.7,64.03 100.02,64.03 101.45,65.46 101.45,67.02 101.38,67.08 101.38,67.68 v3(101.81,68.1)
  IN2 w0.203: v3(97.54,41.03) 97.54,42.26 98.25,42.98 98.25,49.33 96.04,51.54 95.18,51.54 93.96,52.76 93.96,54.34 93.76,54.54 93.35,54.54 93.15,54.34 93.15,52.2 92.91,51.96 92.57,51.96 92.34,52.2 92.34,57.37 96.44,61.47
  BOTTOM w0.102: UC4.K45 v3(101.81,68.1)
  BOTTOM w0.165: JDIMM1.98 98.63,39.44 98.84,39.66 98.84,40.51 98.34,41.01 97.53,41.01 v3(97.54,41.03)
DDR_A_MA1: length 46.9
  IN2 w0.102: 95.34,62.56 95.86,62.56 96.56,63.26 97.61,63.26 97.84,63.5 99,64.66 100.08,64.66 101.05,65.63 101.05,66.38 100.34,67.08 100.34,67.53 v3(100.79,67.98)
  IN2 w0.203: 95.34,62.56 94.69,62.56 94.49,62.36 94.49,61.46 93.67,60.63 93.33,60.63 93.09,60.87 93.09,61.21 93.52,61.64 93.52,61.98 93.29,62.21 92.95,62.21 90.38,59.64 90.38,59.23 90.94,58.67 90.94,57.53 90.73,57.33 90.43,57.33 90.23,57.12 90.23,56.75 90.46,56.51 90.78,56.51 90.98,56.31 90.98,56.02 90.66,55.7 89.8,55.7 89.49,55.4 89.49,51.75 89.92,51.31 91.5,51.31 92.49,50.32 95.54,50.32 97.03,48.82 97.03,44.32 97.24,44.12 v3(97.63,44.12)
  BOTTOM w0.102: v3(100.79,67.98) UC4.H47
  BOTTOM w0.165: JDIMM1.97 98.33,45.83 98.13,45.62 98.13,44.45 97.8,44.12 v3(97.63,44.12)
DDR_A_MA2: length 45
  IN2 w0.102: 97.3,61.47 97.67,61.84 98.7,61.84 99.79,62.93 100.43,63.56 100.46,63.6 100.46,64.16 100.47,64.17 100.47,64.18 101.66,65.37 101.66,67.1 101.59,67.17 101.59,67.49 101.81,67.71 102.03,67.71 102.25,67.94 102.25,69.24 102.34,69.32 102.34,69.91 102.01,70.24 v3(102.01,70.56)
  IN2 w0.203: v3(98.2,39.94) 98.2,42.06 98.86,42.72 98.86,49.58 96.27,52.18 95.4,52.18 94.77,52.81 94.77,56.75 94.52,57 93.96,57 93.76,56.8 93.76,55.41 93.52,55.17 93.18,55.17 92.94,55.41 92.94,57.11 97.3,61.47
  BOTTOM w0.102: UC4.L41 v3(102.01,70.56)
  BOTTOM w0.165: JDIMM1.96 98.03,39.76 v3(98.2,39.94)
DDR_A_MA3: length 46.2
  IN2 w0.102: v3(100.91,68.62) 101.18,68.36 101.18,67 101.25,66.93 101.25,65.54 99.94,64.23 99.62,64.23 99.28,63.89 99.28,63.73 98.36,62.81 96.92,62.81 95.84,61.73
  IN2 w0.203: 95.84,61.73 93.17,59.07 92.84,59.07 92.6,59.31 92.6,59.64 92.86,59.9 92.86,60.24 92.62,60.48 92.28,60.48 91.73,59.92 91.73,52.92 91.49,52.68 91.15,52.68 90.91,52.92 90.91,54.58 90.67,54.82 90.34,54.82 90.1,54.58 90.1,52.13 90.3,51.92 91.75,51.92 92.74,50.93 93.19,50.93 93.39,51.14 93.39,51.57 93.6,51.77 94,51.77 94.21,51.57 94.21,51.14 94.41,50.93 95.79,50.93 97.64,49.08 v3(97.64,45.4)
  BOTTOM w0.102: v3(100.91,68.62) UC4.H44
  BOTTOM w0.165: v3(97.64,45.4) 97.64,45.39 97.73,45.48 JDIMM1.95
DDR_A_MA4: length 46.2
  IN2 w0.102: 95.34,63.21 95.69,63.21 96.03,63.56 97.44,63.56 98.82,64.94 99.8,64.94 v3(100.63,65.77)
  IN2 w0.203: 95.34,63.21 92.88,63.21 88.88,59.21 88.88,58.86 89.08,58.66 90.09,58.66 90.33,58.42 90.33,58.08 90.09,57.85 89.62,57.85 88.88,57.11 88.88,56.77 89.28,56.37 89.28,56.05 88.88,55.65 88.88,51.49 89.67,50.7 91.15,50.7 92.52,49.33 92.81,49.33 93.15,49.68 93.44,49.68 93.73,49.39 93.73,49.1 93.38,48.76 93.38,48.47 94.37,47.49 94.37,44.36 95.42,43.31 96.68,43.31 96.88,43.11 96.88,42.4 96.68,42.2 95.77,42.2 v3(95.61,42.03)
  BOTTOM w0.102: v3(100.63,65.77) UC4.H50
  BOTTOM w0.165: v3(95.61,42.03) 95.61,42.03 95.61,42.04 96.83,40.82 JDIMM1.92
DDR_A_MA5: length 52.6
  IN2 w0.203: v3(96.43,48.14) 96.43,45.45 v3(96.32,45.34)
  BOTTOM w0.102: 96.96,62.36 97.39,62.8 99.99,62.8 100.95,63.76 100.95,64.55 UC4.G53
  BOTTOM w0.165: JDIMM1.91 96.53,45.55 v3(96.32,45.34) ; v3(96.43,48.14) 95.97,48.6 95.97,49.24 96.31,49.58 97.86,49.58 98.42,50.13 98.42,55.49 98.23,55.68 97.95,55.68 97.76,55.49 97.76,50.53 97.58,50.35 97.25,50.35 97.1,50.5 97.1,56.91 96.9,57.1 96.63,57.1 96.44,56.91 96.44,50.53 96.26,50.35 95.93,50.35 95.78,50.5 95.78,61.18 96.96,62.36
DDR_A_MA6: length 47.8
  IN2 w0.102: 92.53,63.72 92.72,63.91 96.66,63.91 98,65.25 99.82,65.25 100.13,65.56 100.13,65.96 v3(100.51,66.34)
  IN2 w0.203: v3(95.48,40.7) 95.13,40.34 95.13,39.71 94.82,39.4 94.37,39.4 94.14,39.64 94.14,43.62 93.76,44 93.76,44.02 93.76,47.24 90.9,50.09 89.42,50.09 88.27,51.24 88.27,57.2 88.03,57.43 87.7,57.43 87.46,57.2 87.46,56.89 87.22,56.65 86.88,56.65 86.65,56.89 86.65,57.84 92.53,63.72
  BOTTOM w0.102: UC4.H49 v3(100.51,66.34)
  BOTTOM w0.165: JDIMM1.90 96.23,40.3 95.84,40.7 v3(95.48,40.7)
DDR_A_MA7: length 45.8
  IN2 w0.102: 92.18,64.24 92.34,64.39 96.85,64.39 98.01,65.55 99.33,65.55 v3(99.54,65.76)
  IN2 w0.203: v3(93.15,42.7) 93.15,46.98 90.65,49.48 89.16,49.48 87.66,50.99 87.66,52.44 87.46,52.65 87.16,52.65 86.92,52.89 86.92,53.22 87.16,53.46 87.46,53.46 87.66,53.66 87.66,54.07 87.46,54.27 86.24,54.27 86.04,54.48 86.04,54.88 86.24,55.09 87.46,55.09 87.66,55.29 87.66,55.7 87.46,55.9 86.24,55.9 86.04,56.1 86.04,58.09 92.18,64.24
  BOTTOM w0.102: v3(99.54,65.76) 99.54,66.23 UC4.D50
  BOTTOM w0.165: JDIMM1.86 95.03,39.63 94.72,39.93 94.72,41.13 v3(93.15,42.7)
DDR_A_MA8: length 53.8
  IN2 w0.203: v3(96.32,44.07) 96.15,44.07 95.67,44.55 95.67,48.67 94.62,49.71 v3(94.37,49.71)
  BOTTOM w0.102: UC4.G52 100.7,65.1 100.7,63.87 99.93,63.1 96.7,63.1 96.13,62.53
  BOTTOM w0.165: v3(94.37,49.71) 95.21,50.55 95.21,59.78 95.01,59.97 94.74,59.97 94.55,59.78 94.55,50.95 94.35,50.75 94.08,50.75 93.88,50.95 93.88,58.59 93.69,58.78 93.42,58.78 93.22,58.59 93.22,57.55 93.03,57.36 92.76,57.36 92.56,57.55 92.56,58.96 96.13,62.53 ; v3(96.32,44.07) 95.85,44.54 95.85,45.57 95.93,45.65 JDIMM1.89
DDR_A_MA9: length 51.7
  IN2 w0.203: v3(94.98,45.11) 94.98,48.09 v3(94.77,48.29)
  BOTTOM w0.102: UC4.E52 100.02,64.82 100.02,64.34 99.11,63.43 96.22,63.43 95.73,62.93
  BOTTOM w0.165: v3(94.77,48.29) 93.98,48.29 93.31,48.96 93.31,56.6 93.12,56.79 92.85,56.79 92.65,56.6 92.65,48.47 92.46,48.28 92.19,48.28 91.99,48.47 91.99,57.51 91.8,57.7 91.53,57.7 91.33,57.51 91.33,55.81 91.14,55.61 90.87,55.61 90.67,55.81 90.67,57.88 95.73,62.93 ; v3(94.98,45.11) 94.73,45.36 JDIMM1.85
DDR_A_MA10: length 56.2
  IN2 w0.203: v3(102.22,49.26) 101.96,49 101.96,43.83 101.96,43.56 v3(101.99,43.53)
  BOTTOM w0.102: UC4.K48 101.91,66.56 101.91,65.97 102.12,65.56 102.15,65.52 102.19,65.38 102.19,65.27 102.02,65.1 102.02,64.95 102.16,64.81 102.16,64.24 102.37,64.03 102.37,63.51 102.11,63.25 101.45,63.25 99.6,61.4 99.19,61.4
  BOTTOM w0.165: v3(101.99,43.53) 101.99,43.58 101.6,43.98 101.6,45.43 101.33,45.69 JDIMM1.107 ; v3(102.22,49.26) 103.51,50.55 107.23,50.55 107.65,50.97 107.65,54.77 107.46,54.97 107.18,54.97 106.99,54.77 106.99,51.57 106.8,51.38 106.52,51.38 106.33,51.57 106.33,54.8 106.17,54.96 105.83,54.96 105.67,54.8 105.67,51.6 105.48,51.4 105.2,51.4 105.01,51.6 105.01,54.97 104.5,55.48 102.94,55.48 101.71,56.71 99.72,56.71 97.49,58.94 97.49,60.31 98.58,61.4 99.19,61.4
DDR_A_MA11: length 47.3
  IN2 w0.102: 95.66,65.87 96.27,65.87 97.03,66.63 98.36,66.63 98.52,66.79 99.53,66.79 99.57,66.83 v3(99.57,66.83)
  IN2 w0.203: v3(93.1,41.43) 92.46,42.07 92.46,42.92 92.07,43.32 91.5,43.32 91.17,43.65 91.17,46.14 89.06,48.25 88.68,48.25 84.82,52.11 84.82,58.63 87.18,61 87.18,61.28 86.76,61.71 86.76,62.05 87,62.28 87.34,62.28 87.63,61.99 87.96,61.99 88.2,62.23 88.2,62.57 87.55,63.22 87.55,63.51 88.3,64.27 89.51,64.27 90.96,65.72 93.28,65.72 93.43,65.87 95.66,65.87
  BOTTOM w0.102: v3(99.57,66.83) 100.07,66.33 UC4.E51
  BOTTOM w0.165: v3(93.1,41.43) 93.3,41.43 94.43,40.3 JDIMM1.84
DDR_A_MA12: length 44.9
  IN2 w0.102: 93.25,65 96.21,65 96.63,65.42 97.59,65.42 98.09,65.92 99.12,65.92 99.42,66.22 99.59,66.22 99.95,66.58 v3(99.95,67.33)
  IN2 w0.203: 93.25,65 92.08,65 91.82,64.74 91.53,64.74 91.33,64.94 91.04,64.94 90.76,64.65 90.76,64.36 90.96,64.16 90.96,63.87 90.12,63.04 89.74,63.04 89.13,63.66 88.79,63.66 88.55,63.42 88.55,63.08 89.19,62.44 89.19,62.11 85.43,58.35 85.43,53.86 85.63,53.65 86.08,53.65 86.29,53.45 86.29,53.05 86.08,52.84 85.63,52.84 85.43,52.64 85.43,52.36 88.91,48.87 89.29,48.87 91.78,46.39 91.78,45.89 91.78,45.89 91.78,44.53 92.31,44 92.34,44 v3(92.44,43.9)
  BOTTOM w0.102: UC4.F47 100.35,67.74 v3(99.95,67.33)
  BOTTOM w0.165: JDIMM1.83 94.13,45.37 92.66,43.9 v3(92.44,43.9)
DDR_A_MA13: length 51.6
  IN2 w0.203: v3(104.47,43.41) 103.82,44.07 103.82,46.97 105.13,48.28 105.13,48.84 104.51,49.46 v3(104.22,49.46)
  BOTTOM w0.102: 98.61,61.98 99.74,61.98 101.5,63.74 101.5,64.28 101.57,64.34 101.57,65.07 UC4.J51
  BOTTOM w0.165: JDIMM1.119 104.93,43.88 v3(104.47,43.41) ; v3(104.22,49.46) 103.66,49.46 102.84,48.63 101.93,48.63 101.58,48.98 101.58,50.11 102.2,50.73 102.2,51.4 102.37,51.56 104.27,51.56 104.44,51.73 104.44,52.06 104.27,52.22 102.37,52.22 102.2,52.39 102.2,52.72 102.37,52.88 104.27,52.88 104.44,53.05 104.44,53.38 104.27,53.54 102.37,53.54 102.2,53.71 102.2,54.04 102.37,54.2 104.27,54.2 104.44,54.37 104.44,54.7 104.27,54.87 102.37,54.87 102.2,55.03 102.2,55.41 102.01,55.6 101.74,55.6 101.54,55.41 101.54,54.46 101.35,54.26 101.08,54.26 100.88,54.46 100.88,55.7 100.45,56.14 99.48,56.14 96.92,58.7 96.92,60.55 98.35,61.98 98.61,61.98
DDR_A_MA14: length 50.1
  IN2 w0.203: v3(89.06,47.38) 89.06,46.99 90.56,45.49 90.56,43.01 92.17,41.39 92.17,40.99 v3(93.23,39.93)
  BOTTOM w0.102: 94.51,64.15 95.27,64.9 95.79,64.9 96.72,65.83 96.72,66.4 96.98,66.66 97.52,66.66 97.68,66.82 98.02,66.82 UC4.B49
  BOTTOM w0.165: 94.51,64.15 92.65,64.15 86.29,57.79 86.29,57.51 86.48,57.32 86.75,57.32 90.42,60.99 90.7,60.99 90.89,60.8 90.89,60.52 86.32,55.95 86.32,51.77 88.89,49.19 88.89,48.3 89.27,47.92 89.27,47.59 v3(89.06,47.38) ; JDIMM1.80 v3(93.23,39.93)
DDR_A_MA15: length 52.2
  IN2 w0.203: v3(91.29,41.38) 91.29,41.41 89.95,42.75 v3(89.95,43.92)
  BOTTOM w0.102: 94.92,63.74 95.63,64.46 96.07,64.46 97.65,66.03 98.2,66.03 UC4.B50
  BOTTOM w0.165: v3(91.29,41.38) 91.64,41.38 92.63,40.39 JDIMM1.78 ; 94.92,63.74 94.75,63.57 92.88,63.57 91.04,61.73 91.04,61.46 91.23,61.26 91.5,61.26 93.11,62.86 93.38,62.86 93.57,62.67 93.57,62.4 86.89,55.71 86.89,52.52 87.08,52.32 87.35,52.32 87.55,52.52 87.55,55.12 87.71,55.28 88.04,55.28 88.21,55.12 88.21,50.68 88.4,50.49 88.67,50.49 88.87,50.68 88.87,51.64 89.06,51.84 89.34,51.84 89.53,51.64 89.53,49.36 89.95,48.94 89.95,46.67 89.31,46.03 89.31,45.19 89.52,44.99 89.52,44.35 v3(89.95,43.92)
DDR_A_ODT0: length 59.8
  IN2 w0.102: v3(104.81,70.24) 104.88,70.24 105.87,69.25 105.87,63.88 106.99,62.76 106.99,62.17
  IN2 w0.203: 106.99,62.17 106.99,58.86 112.86,52.99 114.34,52.99 114.94,52.39 114.94,48.29 114.74,48.08 114.33,48.08 114.13,48.29 114.13,51.69 113.81,52.02 113.52,52.02 113.32,51.81 113.32,48.27 113.08,48.03 112.74,48.03 112.5,48.27 112.5,51.91 112.27,52.15 111.93,52.15 111.69,51.91 111.69,47.1 109.94,45.35 109.94,44.76 109.59,44.41 109,44.41 106.65,42.05 105.99,42.05 105.21,41.28 v3(104.73,41.28)
  BOTTOM w0.102: v3(104.81,70.24) UC4.T41
  BOTTOM w0.165: JDIMM1.116 104.03,40.58 v3(104.73,41.28)
